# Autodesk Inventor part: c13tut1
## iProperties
Created: 2002-04
Part Number: c13tut1
Document SubType Name: Modeling
Control State: 0
Master: False
Checked Out: False
Shininess: 64.0
Angle Display Precision: 2
Document Length Units: 11269
Document Angle Units: 11279
Document Time Units: 11290
Document Mass Units: 11283
Document Length Units Precision: 3
Document Angle Units Precision: 2
Compacted: True
Density: 0.0
Volumn: 0.0
Area: 0.0
PropertySet Name: Model Information
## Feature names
1. Extrusion1
2. Fillet1
